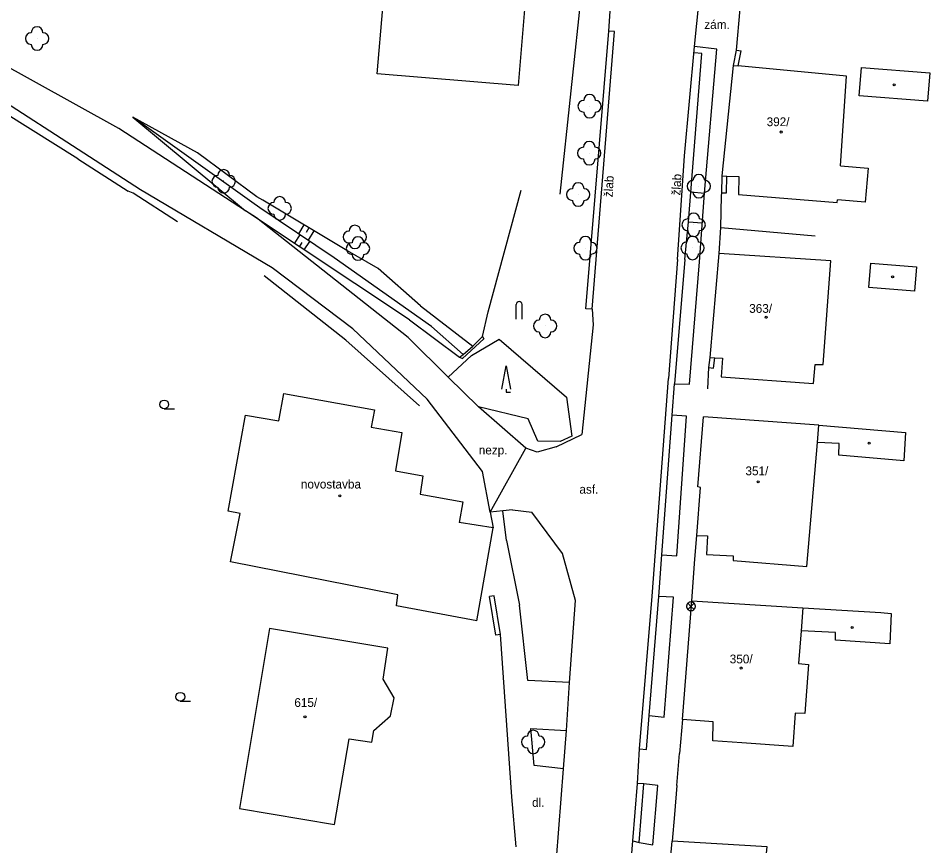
# Model space of a CAD drawing. Extents: x -737488 to -734267, y -1145775 to -1142573.
# Drawn here: x -736723.4 to -736645.6, y -1144564.3 to -1144493.7 of the extents above; entities that cross this region are included whole.
import ezdxf

# ---------------------------------------------------------------- set-up
doc = ezdxf.new("R2010")
doc.units = 0
for name, color, linetype in [('Vrstva 1', 7, 'Continuous'), ('Vrstva 10', 7, 'Continuous'), ('Vrstva 11', 7, 'Continuous'), ('Vrstva 12', 7, 'Continuous'), ('Vrstva 14', 7, 'Continuous'), ('Vrstva 3', 7, 'Continuous'), ('Vrstva 4', 7, 'Continuous'), ('Vrstva 5', 7, 'Continuous'), ('Vrstva 6', 7, 'Continuous'), ('Vrstva 8', 7, 'Continuous'), ('Vrstva 9', 7, 'Continuous')]:
    doc.layers.add(name, color=color, linetype=linetype)

# ---------------------------------------------------------------- blocks, each defined once
blk = doc.blocks.new('1.030')
at = {"layer": 'Vrstva 1'}
for points in [[(-0.53, 0.53), (-0.57, 0.49), (-0.6, 0.45), (-0.63, 0.41), (-0.66, 0.36), (-0.68, 0.32), (-0.7, 0.27), (-0.72, 0.22), (-0.73, 0.17), (-0.74, 0.12), (-0.75, 0.07), (-0.75, 0.01), (-0.75, -0.04), (-0.74, -0.09), (-0.74, -0.14), (-0.72, -0.19), (-0.71, -0.24), (-0.69, -0.29), (-0.67, -0.34), (-0.64, -0.39), (-0.61, -0.43), (-0.58, -0.47), (-0.53, -0.53), (0, 0)], [(0.53, -0.53), (0.57, -0.49), (0.6, -0.45), (0.63, -0.41), (0.66, -0.37), (0.68, -0.32), (0.7, -0.27), (0.72, -0.22), (0.73, -0.17), (0.74, -0.12), (0.75, -0.07), (0.75, -0.01), (0.75, 0.04), (0.75, 0.09), (0.74, 0.14), (0.73, 0.19), (0.71, 0.24), (0.69, 0.29), (0.67, 0.34), (0.64, 0.39), (0.62, 0.43), (0.58, 0.47), (0.53, 0.53), (0, 0)]]:
    blk.add_lwpolyline(points, close=True, dxfattribs=at)
for start, end in [(44.9922, 135.0078), (224.9922, 315.0078)]:
    blk.add_arc((0, 0), 0.75, start, end, dxfattribs=at)
blk = doc.blocks.new('3.130')
at = {"layer": 'Vrstva 1'}
blk.add_circle((0, 0), 0.001, dxfattribs=at)
for centre, start, end in [((0, 1), 0, 180), ((-1, 0), 90, 270), ((1, 0), 270, 90), ((0, -1), 180, 360)]:
    blk.add_arc(centre, 1, start, end, dxfattribs=at)
blk = doc.blocks.new('3.040')
at = {"layer": 'Vrstva 1'}
blk.add_line((0, -0.75), (1.75, -0.75), dxfattribs=at)
blk.add_circle((0, 0), 0.75, dxfattribs=at)
blk = doc.blocks.new('3.090')
at = {"layer": 'Vrstva 1'}
for points in [[(-0.75, 0), (0, 4), (0.75, 0)], [(0, 0), (0, -0.5), (0.75, -0.5)]]:
    blk.add_lwpolyline(points, dxfattribs=at)
blk = doc.blocks.new('4.020')
at = {"layer": 'Vrstva 1'}
blk.add_circle((0, 0), 0.175, dxfattribs=at)
blk = doc.blocks.new('4.140')
at = {"layer": 'Vrstva 1'}
for p, q in [((-0.5, 0), (-0.5, 2.5)), ((0.5, 0), (0.5, 2.5))]:
    blk.add_line(p, q, dxfattribs=at)
blk.add_arc((0, 2.5), 0.5, 0, 180, dxfattribs=at)

msp = doc.modelspace()

# ---------------------------------------------------------------- linework, layer by layer
at = {"layer": 'Vrstva 10'}
for points in [[(-736673, -1144494.78), (-736672.83, -1144492.24)], [(-736665.68, -1144496.09), (-736665.29, -1144492.16)], [(-736674.95, -1144518.5), (-736673, -1144494.78)], [(-736674.43, -1144518.54), (-736672.51, -1144494.81)], [(-736672.51, -1144494.81), (-736673, -1144494.78)], [(-736714.83, -1144503.1), (-736729.15, -1144495.17)], [(-736666.53, -1144505.43), (-736665.68, -1144496.09)], [(-736663.79, -1144496.32), (-736665.68, -1144496.09)], [(-736664.83, -1144508.61), (-736663.79, -1144496.32)], [(-736712.98, -1144508.33), (-736730.33, -1144497.13)], [(-736666.21, -1144511.07), (-736665.05, -1144496.71)], [(-736665.05, -1144496.71), (-736665.73, -1144496.65)], [(-736704.02, -1144510.12), (-736714.83, -1144503.1)], [(-736667.13, -1144514.29), (-736666.53, -1144505.43)], [(-736701.72, -1144515), (-736712.98, -1144508.33)], [(-736666, -1144508.52), (-736664.83, -1144508.61)], [(-736665.26, -1144514.48), (-736664.83, -1144508.61)], [(-736703.07, -1144510.72), (-736704.02, -1144510.12)], [(-736690.13, -1144520.94), (-736703.07, -1144510.72)], [(-736666.51, -1144514.28), (-736666.21, -1144511.07)], [(-736666.21, -1144511.07), (-736665.02, -1144511.16)], [(-736667.13, -1144514.29), (-736667.91, -1144524.44)], [(-736666.51, -1144514.28), (-736667.39, -1144524.89)], [(-736666.12, -1144524.94), (-736665.26, -1144514.48)], [(-736694.84, -1144520.21), (-736701.72, -1144515)], [(-736674.43, -1144518.54), (-736674.95, -1144518.5)], [(-736674.43, -1144518.54), (-736674.35, -1144519.87)], [(-736674.35, -1144519.87), (-736675.29, -1144529.24)], [(-736688.51, -1144526.2), (-736694.84, -1144520.21)], [(-736686.72, -1144524.34), (-736690.13, -1144520.94)], [(-736684.11, -1144526.86), (-736686.72, -1144524.34)], [(-736669.3, -1144543.04), (-736667.91, -1144524.44)], [(-736667.6, -1144527.57), (-736667.39, -1144524.89)], [(-736667.39, -1144524.89), (-736666.12, -1144524.94)], [(-736683.77, -1144532.4), (-736688.51, -1144526.2)], [(-736680.07, -1144530.4), (-736684.11, -1144526.86)], [(-736668.49, -1144539.5), (-736667.6, -1144527.57)], [(-736666.36, -1144527.66), (-736667.6, -1144527.57)], [(-736667.21, -1144539.59), (-736666.36, -1144527.66)], [(-736677.5, -1144530.28), (-736675.29, -1144529.24)], [(-736683.14, -1144535.85), (-736680.07, -1144530.4)], [(-736679.11, -1144530.74), (-736680.07, -1144530.4)], [(-736677.5, -1144530.28), (-736679.11, -1144530.74)], [(-736683.14, -1144535.85), (-736683.77, -1144532.4)], [(-736682.05, -1144535.75), (-736683.14, -1144535.85)], [(-736683.14, -1144535.85), (-736682.86, -1144537.21)], [(-736681.21, -1144535.65), (-736682.05, -1144535.75)], [(-736681.74, -1144538.27), (-736682.05, -1144535.75)], [(-736681.21, -1144535.65), (-736679.56, -1144535.86)], [(-736676.96, -1144539.39), (-736679.56, -1144535.86)], [(-736681.74, -1144538.27), (-736680.63, -1144543.8)], [(-736675.83, -1144543.39), (-736676.96, -1144539.39)], [(-736668.74, -1144543.07), (-736668.49, -1144539.5)], [(-736668.49, -1144539.5), (-736667.21, -1144539.59)], [(-736670.37, -1144556.07), (-736669.3, -1144543.04)], [(-736669.55, -1144553.21), (-736668.74, -1144543.07)], [(-736667.47, -1144543.13), (-736668.74, -1144543.07)], [(-736668.29, -1144553.37), (-736667.47, -1144543.13)], [(-736679.92, -1144550.23), (-736680.63, -1144543.8)], [(-736676.36, -1144550.4), (-736675.83, -1144543.39)], [(-736676.36, -1144550.4), (-736679.92, -1144550.23)], [(-736676.61, -1144554.5), (-736676.36, -1144550.4)], [(-736669.79, -1144556.11), (-736669.55, -1144553.21)], [(-736669.55, -1144553.21), (-736668.29, -1144553.37)], [(-736679.36, -1144557.49), (-736679.67, -1144554.32)], [(-736679.67, -1144554.32), (-736676.61, -1144554.5)], [(-736676.86, -1144557.77), (-736676.61, -1144554.5)], [(-736670.56, -1144559.03), (-736670.37, -1144556.07)], [(-736670.37, -1144556.07), (-736669.79, -1144556.11)], [(-736676.86, -1144557.77), (-736679.36, -1144557.49)], [(-736677.46, -1144565.47), (-736676.86, -1144557.77)], [(-736670.96, -1144563.91), (-736670.56, -1144559.03)], [(-736670, -1144559.07), (-736670.56, -1144559.03)], [(-736670.4, -1144564.06), (-736670, -1144559.07)], [(-736668.81, -1144559.2), (-736670, -1144559.07)], [(-736669.25, -1144564.26), (-736668.81, -1144559.2)], [(-736671.46, -1144570.33), (-736670.96, -1144563.91)], [(-736670.96, -1144563.91), (-736670.4, -1144564.06)], [(-736670.4, -1144564.06), (-736669.25, -1144564.26)]]:
    msp.add_lwpolyline(points, dxfattribs=at)
at = {"layer": 'Vrstva 11'}
for points in [[(-736684.73, -1144522.47), (-736682.36, -1144521.09)], [(-736682.36, -1144521.09), (-736676.6, -1144526.05)], [(-736686.72, -1144524.34), (-736684.73, -1144522.47)], [(-736676.6, -1144526.05), (-736676.15, -1144529.36)], [(-736679.87, -1144527.9), (-736684.11, -1144526.86)], [(-736679.06, -1144529.79), (-736679.87, -1144527.9)], [(-736677.15, -1144529.82), (-736679.06, -1144529.79)], [(-736676.15, -1144529.36), (-736677.15, -1144529.82)]]:
    msp.add_lwpolyline(points, dxfattribs=at)
at = {"layer": 'Vrstva 12'}
for points in [[(-736713.61, -1144502.14), (-736704.02, -1144510.12)], [(-736703.46, -1144509.38), (-736713.61, -1144502.14)], [(-736708.09, -1144505.19), (-736713.61, -1144502.14)], [(-736703.04, -1144508.94), (-736708.09, -1144505.19)], [(-736702.53, -1144509.23), (-736703.04, -1144508.94)], [(-736683.31, -1144518.74), (-736680.47, -1144508.37)], [(-736702.78, -1144509.86), (-736703.46, -1144509.38)], [(-736695.49, -1144513.43), (-736702.53, -1144509.23)], [(-736690, -1144519.45), (-736704.02, -1144510.12)], [(-736688.13, -1144520.02), (-736696.44, -1144514.15), (-736702.78, -1144509.86)], [(-736699.03, -1144511.32), (-736699.49, -1144512.08)], [(-736698.6, -1144511.57), (-736698.84, -1144511.97)], [(-736698.18, -1144511.83), (-736698.66, -1144512.64)], [(-736699.82, -1144512.91), (-736699.34, -1144512.19)], [(-736699.4, -1144513.19), (-736699.16, -1144512.83)], [(-736698.99, -1144513.47), (-736698.51, -1144512.75)], [(-736692.68, -1144515.04), (-736695.49, -1144513.43)], [(-736689.07, -1144518.23), (-736692.68, -1144515.04)], [(-736689.07, -1144518.23), (-736684.6, -1144521.69)], [(-736683.77, -1144520.85), (-736683.31, -1144518.74)], [(-736690, -1144519.45), (-736685.74, -1144522.63)], [(-736688.13, -1144520.02), (-736685.44, -1144522.4)]]:
    msp.add_lwpolyline(points, dxfattribs=at)
at = {"layer": 'Vrstva 4'}
for points in [[(-736662.35, -1144497.73), (-736662.1, -1144496.4)], [(-736662.1, -1144496.4), (-736661.71, -1144496.47)], [(-736661.95, -1144497.76), (-736661.71, -1144496.47)], [(-736663.34, -1144507.14), (-736662.35, -1144497.73)], [(-736662.35, -1144497.73), (-736661.95, -1144497.76)], [(-736663.36, -1144508.6), (-736663.34, -1144507.14)], [(-736663.34, -1144507.14), (-736662.94, -1144507.17)], [(-736662.96, -1144508.6), (-736662.94, -1144507.17)], [(-736663.36, -1144508.6), (-736662.96, -1144508.6)], [(-736664.34, -1144522.64), (-736663.58, -1144513.78)], [(-736664.47, -1144523.51), (-736664.34, -1144522.64)], [(-736664.34, -1144522.64), (-736663.94, -1144522.67)], [(-736664.07, -1144523.57), (-736663.94, -1144522.67)], [(-736664.47, -1144523.51), (-736664.07, -1144523.57)], [(-736665.41, -1144533.71), (-736664.93, -1144527.71)], [(-736665.49, -1144537.84), (-736665.17, -1144533.76)], [(-736665.17, -1144533.76), (-736665.41, -1144533.71)], [(-736682.86, -1144537.21), (-736685.76, -1144536.75)], [(-736684.26, -1144545.15), (-736682.86, -1144537.21)], [(-736682.79, -1144542.99), (-736683.18, -1144543.05)], [(-736682.64, -1144546.36), (-736683.18, -1144543.05)], [(-736682.25, -1144546.3), (-736682.79, -1144542.99)], [(-736684.26, -1144545.15), (-736691.12, -1144543.86)], [(-736666.71, -1144553.56), (-736665.91, -1144543.44)], [(-736682.25, -1144546.3), (-736682.64, -1144546.36)], [(-736668.23, -1144570.81), (-736667.6, -1144563.94)]]:
    msp.add_lwpolyline(points, dxfattribs=at)
at = {"layer": 'Vrstva 5'}
for points in [[(-736692.76, -1144498.42), (-736691.81, -1144487.13)], [(-736679.8, -1144488.14), (-736680.75, -1144499.43)], [(-736653.24, -1144506.3), (-736652.71, -1144498.63), (-736661.95, -1144497.76)], [(-736651.63, -1144500.31), (-736651.44, -1144497.89)], [(-736651.44, -1144497.89), (-736645.61, -1144498.34)], [(-736680.75, -1144499.43), (-736692.76, -1144498.42)], [(-736645.61, -1144498.34), (-736645.8, -1144500.76)], [(-736645.8, -1144500.76), (-736651.63, -1144500.31)], [(-736653.24, -1144506.3), (-736650.86, -1144506.5), (-736651.11, -1144509.38), (-736653.49, -1144509.18)], [(-736662.94, -1144507.17), (-736661.9, -1144507.21), (-736661.94, -1144508.74), (-736653.52, -1144509.41), (-736653.49, -1144509.18)], [(-736663.94, -1144522.67), (-736663.3, -1144522.71), (-736663.4, -1144524.29), (-736655.52, -1144524.87), (-736655.39, -1144523.26), (-736654.72, -1144523.26), (-736654.04, -1144514.4), (-736663.58, -1144513.78)], [(-736650.82, -1144516.69), (-736650.65, -1144514.61)], [(-736650.65, -1144514.61), (-736646.75, -1144514.92)], [(-736646.75, -1144514.92), (-736646.91, -1144517)], [(-736646.91, -1144517), (-736650.82, -1144516.69)], [(-736691.12, -1144543.86), (-736691.01, -1144542.91), (-736705.3, -1144540.11), (-736704.46, -1144535.96), (-736705.48, -1144535.76), (-736704, -1144527.57), (-736701.16, -1144528.07), (-736700.74, -1144525.74), (-736693, -1144527.11), (-736693.27, -1144528.61), (-736690.67, -1144529.06), (-736691.21, -1144532.34), (-736688.86, -1144532.75), (-736689.11, -1144534.31), (-736685.45, -1144534.98), (-736685.76, -1144536.75)], [(-736665.49, -1144537.84), (-736664.58, -1144537.89), (-736664.66, -1144539.47), (-736662.4, -1144539.59), (-736662.4, -1144539.99), (-736656.1, -1144540.5), (-736655.2, -1144529.9), (-736655.08, -1144528.43), (-736664.93, -1144527.71)], [(-736655.08, -1144528.43), (-736647.67, -1144529.06), (-736647.83, -1144531.48), (-736653.37, -1144531), (-736653.33, -1144530.01), (-736655.2, -1144529.9)], [(-736665.91, -1144543.44), (-736656.45, -1144544.03), (-736656.59, -1144546), (-736656.8, -1144548.78), (-736655.97, -1144548.86), (-736656.27, -1144553.06), (-736657.1, -1144553.03), (-736657.31, -1144555.86), (-736661.65, -1144555.56), (-736664.13, -1144555.39), (-736664.09, -1144553.75), (-736666.71, -1144553.56)], [(-736656.45, -1144544.03), (-736649.8, -1144544.44), (-736648.9, -1144544.5), (-736649.01, -1144547.09), (-736653.65, -1144546.79), (-736653.65, -1144546.13), (-736656.59, -1144546)], [(-736701.96, -1144545.78), (-736704.51, -1144561.15), (-736696.42, -1144562.52), (-736695.15, -1144555.21), (-736693.23, -1144555.51), (-736693.06, -1144554.5), (-736691.62, -1144553.25), (-736691.33, -1144551.71), (-736692.26, -1144550.12), (-736691.86, -1144547.47), (-736701.96, -1144545.78)], [(-736668.23, -1144570.81), (-736660.17, -1144571.39), (-736659.82, -1144567.83), (-736659.49, -1144564.43), (-736667.6, -1144563.94)]]:
    msp.add_lwpolyline(points, dxfattribs=at)
at = {"layer": 'Vrstva 9'}
for points in [[(-736677.16, -1144508.7), (-736675.27, -1144491.03)], [(-736662.1, -1144496.4), (-736661.79, -1144492.89)], [(-736718.31, -1144505.68), (-736730.47, -1144498.08)], [(-736718.31, -1144505.68), (-736714.03, -1144508.44)], [(-736713.6, -1144508.62), (-736714.03, -1144508.44)], [(-736709.81, -1144511.07), (-736713.6, -1144508.62)], [(-736663.43, -1144511.56), (-736663.37, -1144508.84)], [(-736663.37, -1144508.84), (-736663.36, -1144508.6)], [(-736663.58, -1144513.78), (-736663.43, -1144511.56)], [(-736663.43, -1144511.56), (-736655.38, -1144512.26)], [(-736695.45, -1144521.18), (-736702.4, -1144515.69)], [(-736689.16, -1144526.77), (-736695.45, -1144521.18)], [(-736685.49, -1144522.73), (-736683.68, -1144521.06)], [(-736684.6, -1144521.69), (-736683.77, -1144520.85)], [(-736683.77, -1144520.85), (-736683.68, -1144521.06)], [(-736685.44, -1144522.4), (-736684.6, -1144521.69)], [(-736685.74, -1144522.63), (-736685.44, -1144522.4)], [(-736685.74, -1144522.63), (-736685.49, -1144522.73)], [(-736664.56, -1144525.34), (-736664.47, -1144523.51)], [(-736665.65, -1144539.88), (-736665.49, -1144537.84)], [(-736665.91, -1144543.44), (-736665.65, -1144539.88)], [(-736681.27, -1144560.18), (-736682.25, -1144546.3)], [(-736666.71, -1144553.56), (-736666.98, -1144556.46)], [(-736667.2, -1144559.21), (-736666.98, -1144556.46)], [(-736667.2, -1144559.21), (-736667.39, -1144561.68), (-736667.6, -1144563.94)], [(-736680.9, -1144564.43), (-736681.27, -1144560.18)]]:
    msp.add_lwpolyline(points, dxfattribs=at)

# ---------------------------------------------------------------- block references
at = {"layer": 'Vrstva 1', "xscale": 0.5, "yscale": 0.5}
msp.add_blockref('1.030', (-736665.99, -1144543.9), dxfattribs=at)
at = {"layer": 'Vrstva 11', "xscale": 0.5, "yscale": 0.5}
for p in [(-736721.79, -1144495.42), (-736674.64, -1144501.2), (-736674.67, -1144505.2), (-736705.87, -1144507.61), (-736665.32, -1144508.03), (-736675.61, -1144508.74), (-736701.09, -1144509.92), (-736665.76, -1144511.32), (-736694.67, -1144512.36), (-736694.41, -1144513.35), (-736675, -1144513.32), (-736665.85, -1144513.3), (-736678.44, -1144519.96), (-736679.45, -1144555.48)]:
    msp.add_blockref('3.130', p, dxfattribs=at)
at = {"layer": 'Vrstva 3', "xscale": 0.5, "yscale": 0.5}
for name, p in [('3.090', (-736681.76, -1144525.37)), ('3.040', (-736710.94, -1144526.66)), ('3.040', (-736709.57, -1144551.62))]:
    msp.add_blockref(name, p, dxfattribs=at)
at = {"layer": 'Vrstva 8', "xscale": 0.5, "yscale": 0.5}
for p in [(-736648.65, -1144499.38), (-736658.3, -1144503.4), (-736648.78, -1144515.77), (-736659.58, -1144519.22), (-736650.79, -1144529.97), (-736660.26, -1144533.27), (-736695.96, -1144534.47), (-736652.23, -1144545.7), (-736661.71, -1144549.17), (-736698.93, -1144553.34)]:
    msp.add_blockref('4.020', p, dxfattribs=at)
at = {"layer": 'Vrstva 9', "xscale": 0.5, "yscale": 0.5}
msp.add_blockref('4.140', (-736680.65, -1144519.37), dxfattribs=at)

# ---------------------------------------------------------------- texts
at = {"layer": 'Vrstva 14'}
for s, p in [('zám.', (-736664.85, -1144494.6)), ('nezp.', (-736684.1, -1144530.93)), ('novostavba', (-736699.28, -1144533.84)), ('asf.', (-736675.51, -1144534.28)), ('dl.', (-736679.55, -1144561.02))]:
    msp.add_text(s, height=0.75, dxfattribs=at).set_placement(p)
for p in [(-736672.68, -1144508.98), (-736666.9, -1144508.83)]:
    msp.add_text('žlab', height=0.75, rotation=86.864, dxfattribs=at).set_placement(p)
at = {"layer": 'Vrstva 6'}
for s, p in [('392/', (-736659.53, -1144502.9)), ('363/', (-736661.02, -1144518.84)), ('351/', (-736661.34, -1144532.71)), ('350/', (-736662.68, -1144548.77)), ('615/', (-736699.84, -1144552.49))]:
    msp.add_text(s, height=0.75, dxfattribs=at).set_placement(p)

doc.saveas('drawing.dxf')
